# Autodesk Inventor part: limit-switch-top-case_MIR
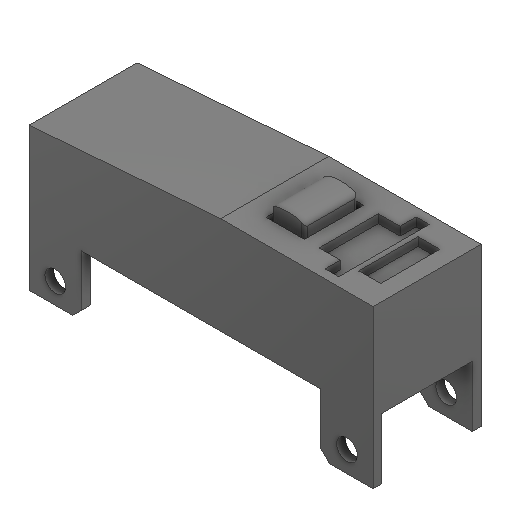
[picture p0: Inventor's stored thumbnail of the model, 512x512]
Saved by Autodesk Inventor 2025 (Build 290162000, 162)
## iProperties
Created: 2025-10
Part Number: limit-switch-top-case_MIR
Material: Generico
Document SubType Name: Modeling
Designer: Ryzen5700u
Density: 1 g/cm^3
Appearance: Default
Author: Ryzen5700u
Revision Number: ANY
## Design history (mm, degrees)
derived "limit-switch-top-case.ipt"
feature "Solido1::limit-switch-top-case.ipt" dims "d0" = 10
tag "Lavorazione contrassegno1"
node "Solido1"
